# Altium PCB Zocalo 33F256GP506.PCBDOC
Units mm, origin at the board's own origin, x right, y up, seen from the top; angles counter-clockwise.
Board outline 80.87 x 74.55 mm, 2 copper layers (Top Layer, Bottom Layer); 8 components, 108 nets, 330 pads, 93 vias.
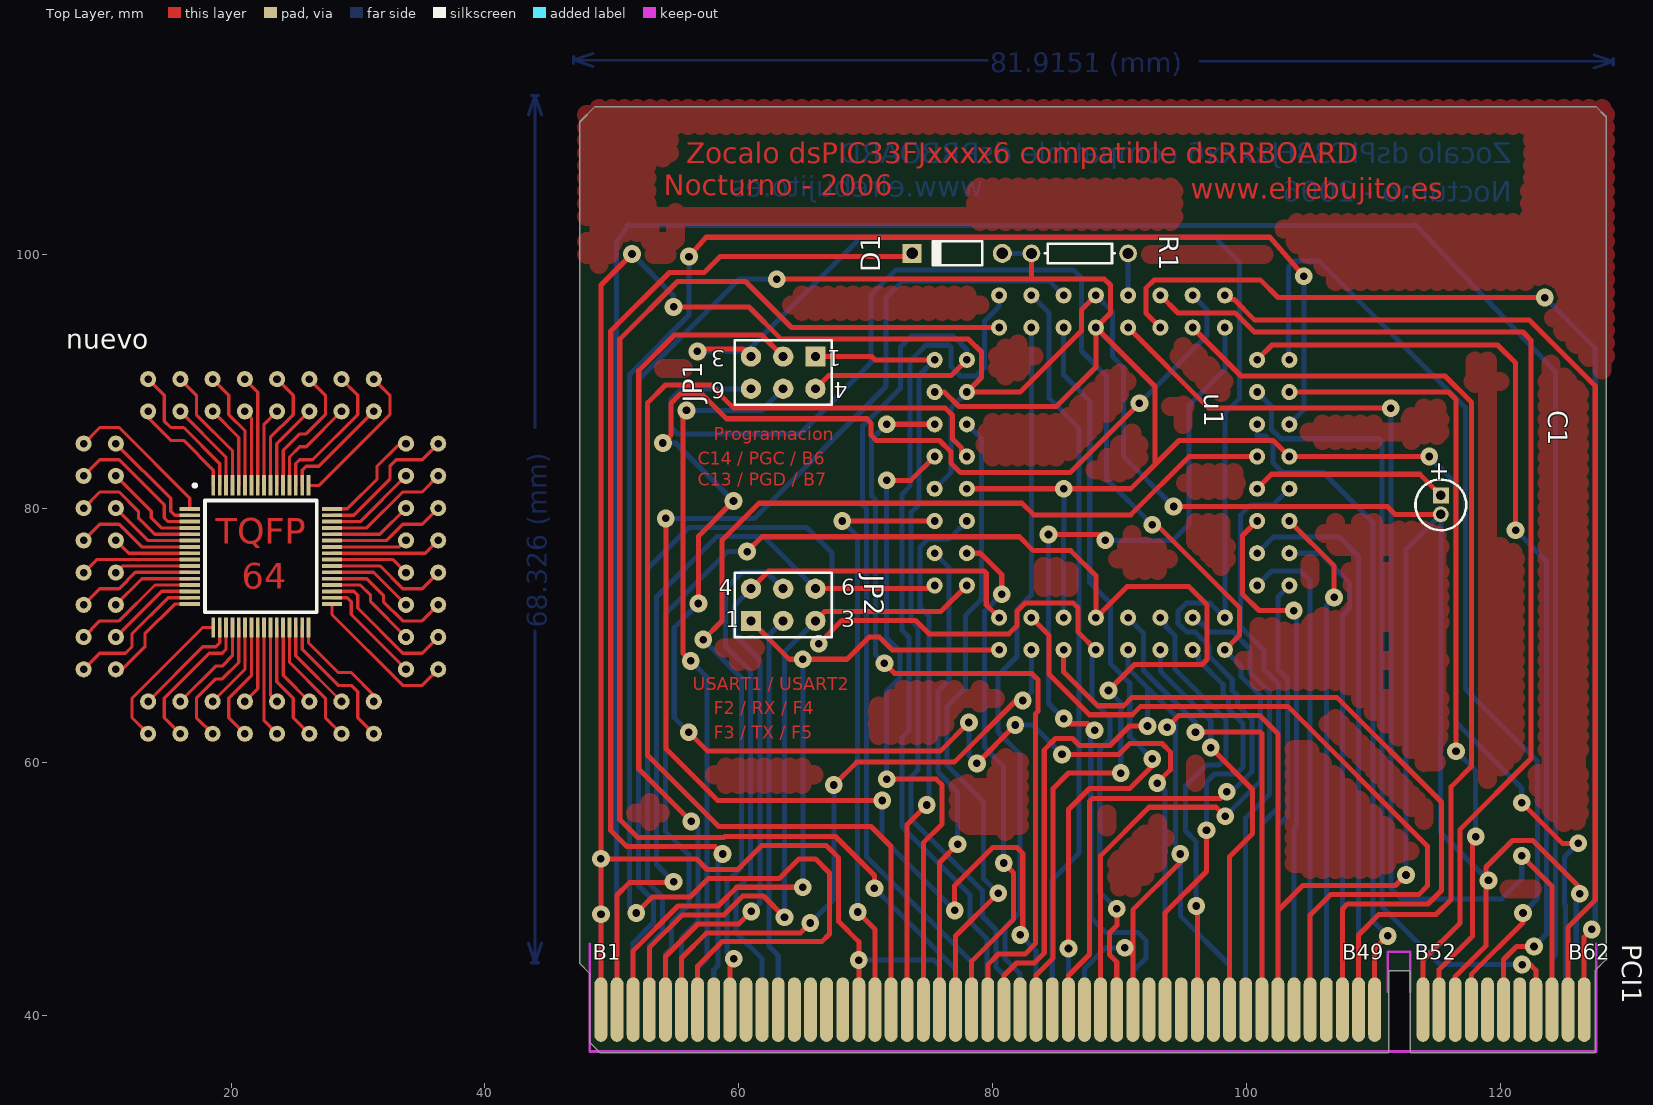
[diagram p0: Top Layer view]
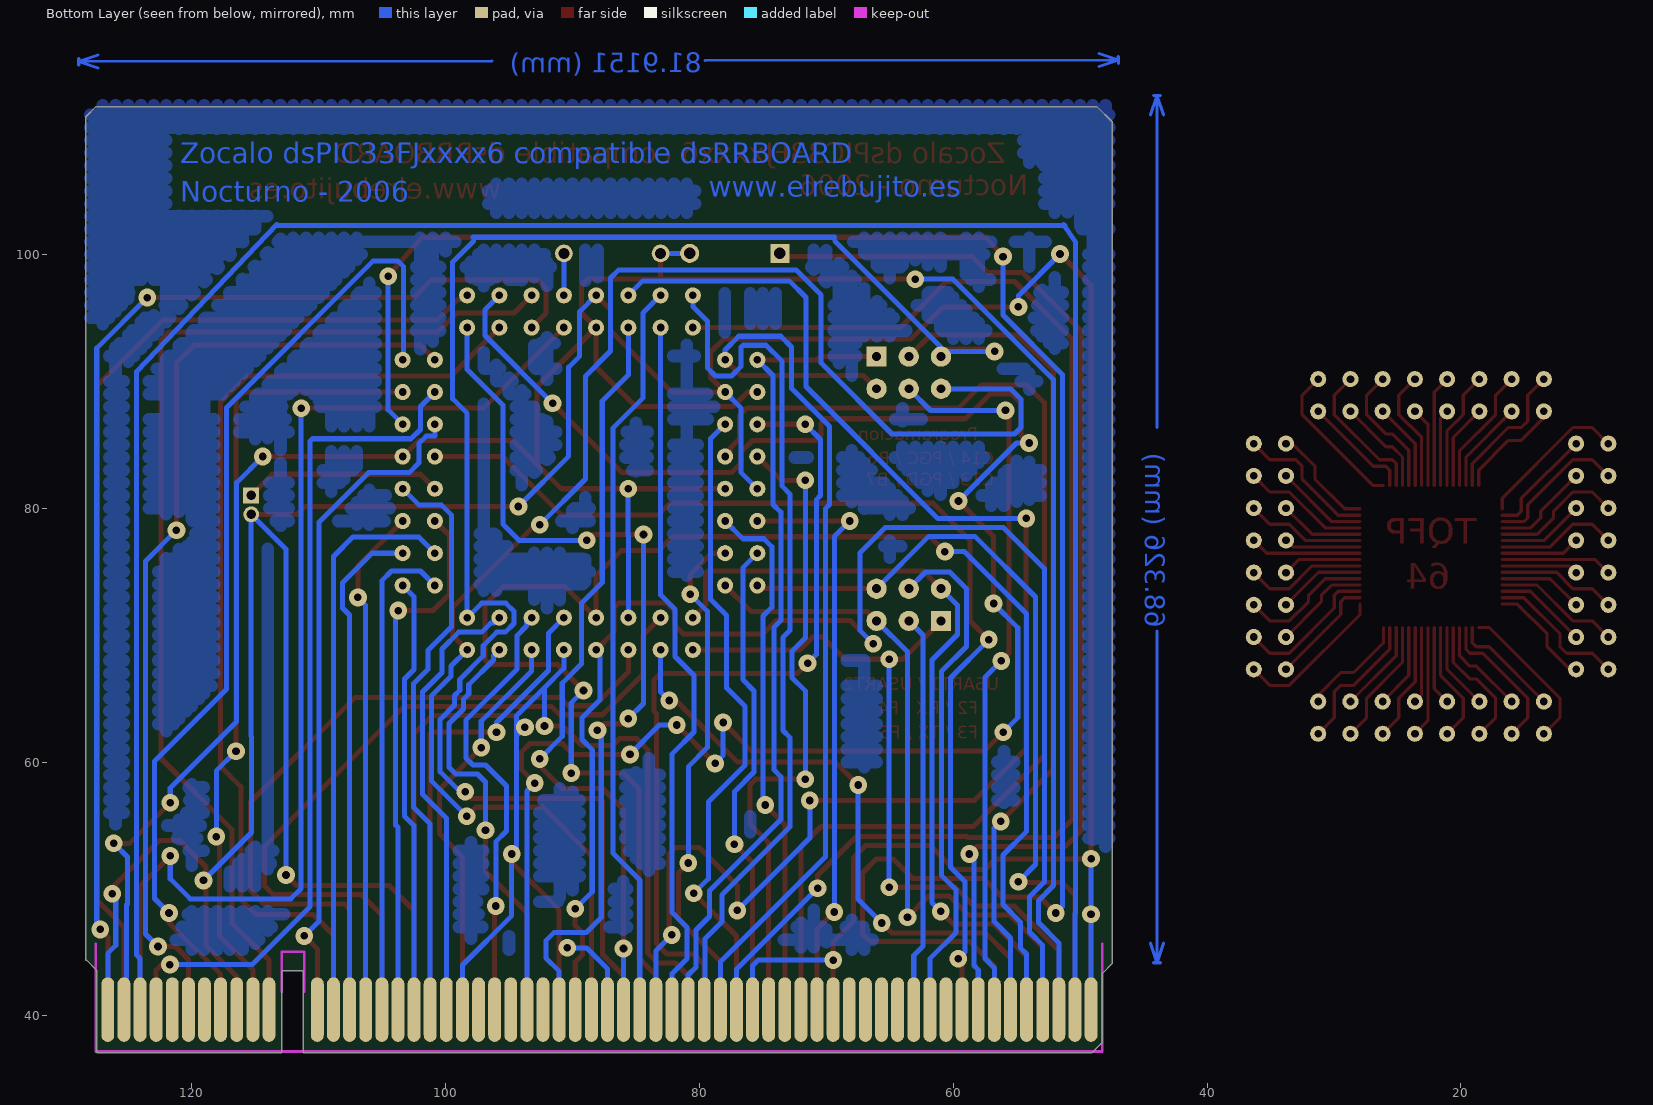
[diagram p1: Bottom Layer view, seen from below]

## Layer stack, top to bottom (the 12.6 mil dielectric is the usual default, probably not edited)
Top Layer: signal copper 0.0356
Dielectric: core 0.32, FR-4, Dk 4.8
Bottom Layer: signal copper 0.0356

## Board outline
128.35,44.4 128.35,110.85 127.55,111.65 48.675,111.65 47.475,110.45 47.475,44.125 48.25,43.35 48.25,37.925 49.075,37.1 111.2,37.1 111.2,43.575 112.9,43.575 112.9,37.1 127.475,37.1 127.475,43.575 128.3,44.4

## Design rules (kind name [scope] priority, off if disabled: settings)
Clearance [All] p1: gap=0.3
ComponentClearance [All] p1: gap=0.254 collisioncheckmode=0
HoleSize [All] p1: absolutevalues=TRUE maxlimit=2.54 minlimit=0.6 maxpercent=80.000 minpercent=20.000
PlaneConnect [All] p1: planeconnectstyle=Relief reliefexpansion=0.5 reliefentries=4 reliefconductorwidth=0.4 reliefairgap=0.3
PolygonConnect [All] p1: connectstyle=Relief reliefconductorwidth=0.4 reliefentries=4 polygonreliefangle="90 Angle"
RoutingLayers [All] p1: top layer=Horizontal bottom layer=Vertical
RoutingVias [All] p1: holewidth=0.6 width=1.4 viastyle="Through Hole" minholewidth=0.6 minwidth=1.4 maxholewidth=0.6 maxwidth=1.4
SolderMaskExpansion [All] p1: expansion=1
TestPointUsage [All] p1: valid=0 allowmultiple=FALSE
Testpoint [All] p1: side=15 testpointundercomponent=TRUE minsize=1.016 maxsize=2.54 preferedsize=1.524 minholesize=0 maxholesize=1.016 preferedholesize=0.813 testpointgrid=0.025 style=1023 order=1234567890
Width [All] p1: maxlimit=0.4 minlimit=0.254 preferedwidth=0.254 toplayer_minwidth=0.4 toplayer_prefwidth=0.4 bottomlayer_minwidth=0.4 bottomlayer_prefwidth=0.4 minimp=50.000000 maximp=50.000000 favimp=50.000000
14 further rules are at their usual default settings.

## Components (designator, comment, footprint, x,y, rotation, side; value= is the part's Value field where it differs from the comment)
C1 "Cap Pol1" CAPPR1.5-4X5 115.316,80.264 r270 top
D1 "BAT85" DIO7.1-3.9x1.9 77.216,100.076 r180 top
JP1 "Header 3X2A" HDR2X3_CEN 66.04,91.948 r180 top
JP2 "Header 3X2A" HDR2X3_CEN 60.96,71.12 r0 top
nuevo "Comment" "TQFP-64 con DIP" 22.352,76.2 r0 top
PCI1 "Conector PCI Macho" PCI_Macho 76.708,45.72 r0 top
R1 "Res1" AXIAL-0.3 86.868,100.076 r0 top
u1 "o33FJ256GP506" "TQFP-64 SOLO DIP" 89.408,82.804 r270 top

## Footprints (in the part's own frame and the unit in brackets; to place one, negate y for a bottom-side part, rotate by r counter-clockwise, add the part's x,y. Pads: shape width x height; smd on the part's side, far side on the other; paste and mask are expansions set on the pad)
AXIAL-0.3 [mm]
  round 1.4 hole 0.85: 1(-3.81,0) 2(3.81,0)
  silkscreen extent -2.77,-0.76 2.77,0.76
CAPPR1.5-4X5 [mm]
  rect 1.25x1.25 hole 0.75: 1(-0.75,0)
  round 1.25 hole 0.75: 2(0.75,0)
  silkscreen extent -2,-2 2,2
DIO7.1-3.9x1.9 [mm]
  round 1.5 hole 0.9: 1(-3.55,0)
  rect 1.5x1.5 hole 0.9: 2(3.55,0)
  silkscreen extent -1.95,-0.95 2.05,0.95
HDR2X3_CEN [mm] "Connector; Header; 3x2 Position"
  rect 1.6x1.6 hole 0.7: 1(0,0)
  round 1.6 hole 0.7: 2(2.54,0) 3(5.08,0) 4(0,2.54) 5(2.54,2.54) 6(5.08,2.54)
  silkscreen extent -1.27,-1.27 6.35,3.81
PCI_Macho [mil] "Conector PCI Macho"
  oval 40x200 smd far side: A1(-1085.31,-205.75) A2(-1035.31,-205.75) A3(-985.31,-205.75) A4(-935.31,-205.75) A5(-885.31,-205.75) A6(-835.31,-205.75) A7(-785.31,-205.75) A8(-735.31,-205.75) A9(-685.31,-205.75) A10(-635.31,-205.75) A11(-585.31,-205.75) A12(-535.31,-205.75) A13(-485.31,-205.75) A14(-435.31,-205.75) A15(-385.31,-205.75) A16(-335.31,-205.75) A17(-285.31,-205.75) A18(-235.31,-205.75) A19(-185.31,-205.75) A20(-135.31,-205.75) A21(-85.31,-205.75) A22(-35.31,-205.75) A23(14.69,-205.75) A24(64.69,-205.75) A25(114.69,-205.75) A26(164.69,-205.75) A27(214.69,-205.75) A28(264.69,-205.75) A29(314.69,-205.75) A30(364.69,-205.75) A31(414.69,-205.75) A32(464.69,-205.75) A33(514.69,-205.75) A34(564.69,-205.75) A35(614.69,-205.75) A36(664.69,-205.75) A37(714.69,-205.75) A38(764.69,-205.75) A39(814.69,-205.75) A40(864.69,-205.75) A41(914.69,-205.75) A42(964.69,-205.75) A43(1014.69,-205.75) A44(1064.69,-205.75) A45(1114.69,-205.75) A46(1164.69,-205.75) A47(1214.69,-205.75) A48(1264.69,-205.75) A49(1314.69,-205.75) A50(1464.69,-205.75) A51(1514.69,-205.75) A52(1564.69,-205.75) A53(1614.69,-205.75) A54(1664.69,-205.75) A55(1714.69,-205.75) A56(1764.69,-205.75) A57(1814.69,-205.75) A58(1864.69,-205.75) A59(1914.69,-205.75) A60(1964.69,-205.75)
  oval 40x200 smd: B1(-1085.31,-205.75) B2(-1035.31,-205.75) B3(-985.31,-205.75) B4(-935.31,-205.75) B5(-885.31,-205.75) B6(-835.31,-205.75) B7(-785.31,-205.75) B8(-735.31,-205.75) B9(-685.31,-205.75) B10(-635.31,-205.75) B11(-585.31,-205.75) B12(-535.31,-205.75) B13(-485.31,-205.75) B14(-435.31,-205.75) B15(-385.31,-205.75) B16(-335.31,-205.75) B17(-285.31,-205.75) B18(-235.31,-205.75) B19(-185.31,-205.75) B20(-135.31,-205.75) B21(-85.31,-205.75) B22(-35.31,-205.75) B23(14.69,-205.75) B24(64.69,-205.75) B25(114.69,-205.75) B26(164.69,-205.75) B27(214.69,-205.75) B28(264.69,-205.75) B29(314.69,-205.75) B30(364.69,-205.75) B31(414.69,-205.75) B32(464.69,-205.75) B33(514.69,-205.75) B34(564.69,-205.75) B35(614.69,-205.75) B36(664.69,-205.75) B37(714.69,-205.75) B38(764.69,-205.75) B39(814.69,-205.75) B40(864.69,-205.75) B41(914.69,-205.75) B42(964.69,-205.75) B43(1014.69,-205.75) B44(1064.69,-205.75) B45(1114.69,-205.75) B46(1164.69,-205.75) B47(1214.69,-205.75) B48(1264.69,-205.75) B49(1314.69,-205.75) B50(1464.69,-205.75) B51(1514.69,-205.75) B52(1564.69,-205.75) B53(1614.69,-205.75) B54(1664.69,-205.75) B55(1714.69,-205.75) B56(1764.69,-205.75) B57(1814.69,-205.75) B58(1864.69,-205.75) B59(1914.69,-205.75) B60(1964.69,-205.75)
  Keep-Out Layer lines w8: -1120.31,-0.75 -1120.31,-335.75 1998.63,-335.75 ; 1354.69,-150.75 1354.69,-25.75 1424.69,-25.75 1424.69,-150.75 ; 2002.57,-335.75 2002.57,-0.75
"TQFP-64 con DIP" [mm]
  round 1.27 hole 0.6: 1(-13.97,8.89) 2(-11.43,8.89) 3(-13.97,6.35) 4(-11.43,6.35) 5(-13.97,3.81) 6(-11.43,3.81) 7(-13.97,1.27) 8(-11.43,1.27) 9(-13.97,-1.27) 10(-11.43,-1.27) 11(-13.97,-3.81) 12(-11.43,-3.81) 13(-13.97,-6.35) 14(-11.43,-6.35) 15(-13.97,-8.89) 16(-11.43,-8.89) 17(-8.89,-13.97) 18(-8.89,-11.43) 19(-6.35,-13.97) 20(-6.35,-11.43) 21(-3.81,-13.97) 22(-3.81,-11.43) 23(-1.27,-13.97) 24(-1.27,-11.43) 25(1.27,-13.97) 26(1.27,-11.43) 27(3.81,-13.97) 28(3.81,-11.43) 29(6.35,-13.97) 30(6.35,-11.43) 31(8.89,-13.97) 32(8.89,-11.43) 33(13.97,-8.89) 34(11.43,-8.89) 35(13.97,-6.35) 36(11.43,-6.35) 37(13.97,-3.81) 38(11.43,-3.81) 39(13.97,-1.27) 40(11.43,-1.27) 41(13.97,1.27) 42(11.43,1.27) 43(13.97,3.81) 44(11.43,3.81) 45(13.97,6.35) 46(11.43,6.35) 47(13.97,8.89) 48(11.43,8.89) 49(8.89,13.97) 50(8.89,11.43) 51(6.35,13.97) 52(6.35,11.43) 53(3.81,13.97) 54(3.81,11.43) 55(1.27,13.97) 56(1.27,11.43) 57(-1.27,13.97) 58(-1.27,11.43) 59(-3.81,13.97) 60(-3.81,11.43) 61(-6.35,13.97) 62(-6.35,11.43) 63(-8.89,13.97) 64(-8.89,11.43)
  rect 1.6x0.3 smd: 1(-5.6,3.75) 2(-5.6,3.25) 3(-5.6,2.75) 4(-5.6,2.25) 5(-5.6,1.75) 6(-5.6,1.25) 7(-5.6,0.75) 8(-5.6,0.25) 9(-5.6,-0.25) 10(-5.6,-0.75) 11(-5.6,-1.25) 12(-5.6,-1.75) 13(-5.6,-2.25) 14(-5.6,-2.75) 15(-5.6,-3.25) 16(-5.6,-3.75) 33(5.6,-3.75) 34(5.6,-3.25) 35(5.6,-2.75) 36(5.6,-2.25) 37(5.6,-1.75) 38(5.6,-1.25) 39(5.6,-0.75) 40(5.6,-0.25) 41(5.6,0.25) 42(5.6,0.75) 43(5.6,1.25) 44(5.6,1.75) 45(5.6,2.25) 46(5.6,2.75) 47(5.6,3.25) 48(5.6,3.75)
  rect 0.3x1.6 smd: 17(-3.75,-5.6) 18(-3.25,-5.6) 19(-2.75,-5.6) 20(-2.25,-5.6) 21(-1.75,-5.6) 22(-1.25,-5.6) 23(-0.75,-5.6) 24(-0.25,-5.6) 25(0.25,-5.6) 26(0.75,-5.6) 27(1.25,-5.6) 28(1.75,-5.6) 29(2.25,-5.6) 30(2.75,-5.6) 31(3.25,-5.6) 32(3.75,-5.6) 49(3.75,5.6) 50(3.25,5.6) 51(2.75,5.6) 52(2.25,5.6) 53(1.75,5.6) 54(1.25,5.6) 55(0.75,5.6) 56(0.25,5.6) 57(-0.25,5.6) 58(-0.75,5.6) 59(-1.25,5.6) 60(-1.75,5.6) 61(-2.25,5.6) 62(-2.75,5.6) 63(-3.25,5.6) 64(-3.75,5.6)
  Top Layer lines w0.254: -13.97,-8.89 -12.7,-7.62 -10.668,-7.62 -10.16,-7.112 -10.16,-6.096 -7.314,-3.25 -6.298,-3.25 -5.6,-3.25 ; -13.97,-6.35 -12.7,-5.08 -11.176,-5.08 -8.346,-2.25 -5.6,-2.25 ; -13.97,-3.81 -12.7,-2.54 -11.176,-2.54 -9.886,-1.25 -5.6,-1.25 ; -13.97,-1.27 -12.95,-0.25 -5.6,-0.25 ; -13.97,1.27 -12.7,2.54 -11.176,2.54 -9.386,0.75 -5.6,0.75 ; -13.97,3.81 -12.7,5.08 -11.176,5.08 -9.652,3.556 -9.652,3.048 -8.354,1.75 -5.6,1.75 ; -13.97,6.35 -12.7,7.62 -11.176,7.62 -7.62,4.064 -7.62,3.048 -7.322,2.75 -5.6,2.75 ; -13.97,8.89 -12.7,10.16 -11.176,10.16 -5.6,4.584 -5.6,3.75 ; -11.43,-8.89 -10.922,-8.89 -9.144,-7.112 -9.144,-6.096 -6.798,-3.75 -5.6,-3.75 ; -11.43,-6.35 -7.83,-2.75 -5.6,-2.75 ; -11.43,-3.81 -9.37,-1.75 -5.6,-1.75 ; -11.43,-1.27 -10.91,-0.75 -5.6,-0.75 ; -11.43,1.27 -10.41,0.25 -5.6,0.25 ; -11.43,3.81 -8.87,1.25 -5.6,1.25 ; -11.43,6.35 -8.636,3.556 -8.636,3.048 -7.838,2.25 -5.6,2.25 ; -11.43,8.89 -7.112,4.572 -7.112,3.556 -6.806,3.25 -5.6,3.25 ; -8.89,-13.97 -10.16,-12.7 -10.16,-11.176 -4.584,-5.6 -3.75,-5.6 ; -8.89,-11.43 -4.572,-7.112 -3.556,-7.112 -3.25,-6.806 -3.25,-5.6 ; -8.89,11.43 -8.89,10.922 -7.112,9.144 -6.096,9.144 -3.75,6.798 -3.75,5.6 ; -8.89,13.97 -7.62,12.7 -7.62,10.668 -7.112,10.16 -6.096,10.16 -3.25,7.314 -3.25,6.298 -3.25,5.6 ; -6.35,-13.97 -7.62,-12.7 -7.62,-11.176 -4.064,-7.62 -3.048,-7.62 -2.75,-7.322 -2.75,-5.6 ; -6.35,-11.43 -3.556,-8.636 -3.048,-8.636 -2.25,-7.838 -2.25,-5.6 ; -6.35,11.43 -2.75,7.83 -2.75,5.6 ; -6.35,13.97 -5.08,12.7 -5.08,11.176 -2.25,8.346 -2.25,5.6 ; -3.81,-13.97 -5.08,-12.7 -5.08,-11.176 -3.556,-9.652 -3.048,-9.652 -1.75,-8.354 -1.75,-5.6 ; -3.81,-11.43 -1.25,-8.87 -1.25,-5.6 ; -3.81,11.43 -1.75,9.37 -1.75,5.6 ; -3.81,13.97 -2.54,12.7 -2.54,11.176 -1.25,9.886 -1.25,5.6 ; -1.27,-13.97 -2.54,-12.7 -2.54,-11.176 -0.75,-9.386 -0.75,-5.6 ; -1.27,-11.43 -0.25,-10.41 -0.25,-5.6 ; -1.27,11.43 -0.75,10.91 -0.75,5.6 ; -1.27,13.97 -0.25,12.95 -0.25,5.6 ; 0.25,-5.6 0.25,-12.95 1.27,-13.97 ; 0.25,5.6 0.25,10.41 1.27,11.43 ; 0.75,-5.6 0.75,-10.91 1.27,-11.43 ; 0.75,5.6 0.75,9.386 2.54,11.176 2.54,12.7 1.27,13.97 ; 1.25,-5.6 1.25,-9.886 2.54,-11.176 2.54,-12.7 3.81,-13.97 ; 1.25,5.6 1.25,8.87 3.81,11.43 ; 1.75,-5.6 1.75,-9.37 3.81,-11.43 ; 1.75,5.6 1.75,8.354 3.048,9.652 3.556,9.652 5.08,11.176 5.08,12.7 3.81,13.97 ; 2.25,-5.6 2.25,-8.346 5.08,-11.176 5.08,-12.7 6.35,-13.97 ; 2.25,5.6 2.25,7.838 3.048,8.636 3.556,8.636 6.35,11.43 ; 2.75,-5.6 2.75,-7.83 6.35,-11.43 ; 2.75,5.6 2.75,7.322 3.048,7.62 4.064,7.62 7.62,11.176 7.62,12.7 6.35,13.97 ; 3.25,-5.6 3.25,-6.298 3.25,-7.314 6.096,-10.16 7.112,-10.16 7.62,-10.668 7.62,-12.7 8.89,-13.97 ; 3.25,5.6 3.25,6.806 3.556,7.112 4.572,7.112 8.89,11.43 ; 3.75,-5.6 3.75,-6.798 6.096,-9.144 7.112,-9.144 8.89,-10.922 8.89,-11.43 ; 3.75,5.6 4.584,5.6 10.16,11.176 10.16,12.7 8.89,13.97 ; 5.6,-3.75 5.6,-4.584 11.176,-10.16 12.7,-10.16 13.97,-8.89 ; 5.6,-3.25 6.806,-3.25 7.112,-3.556 7.112,-4.572 11.43,-8.89 ; 5.6,-2.75 7.322,-2.75 7.62,-3.048 7.62,-4.064 11.176,-7.62 12.7,-7.62 13.97,-6.35 ; 5.6,-2.25 7.838,-2.25 8.636,-3.048 8.636,-3.556 11.43,-6.35 ; 5.6,-1.75 8.354,-1.75 9.652,-3.048 9.652,-3.556 11.176,-5.08 12.7,-5.08 13.97,-3.81 ; 5.6,-1.25 8.87,-1.25 11.43,-3.81 ; 5.6,-0.75 9.386,-0.75 11.176,-2.54 12.7,-2.54 13.97,-1.27 ; 5.6,-0.25 10.41,-0.25 11.43,-1.27 ; 5.6,0.25 12.95,0.25 13.97,1.27 ; 5.6,0.75 10.91,0.75 11.43,1.27 ; 5.6,1.25 9.886,1.25 11.176,2.54 12.7,2.54 13.97,3.81 ; 5.6,1.75 9.37,1.75 11.43,3.81 ; 5.6,2.25 8.346,2.25 11.176,5.08 12.7,5.08 13.97,6.35 ; 5.6,2.75 7.83,2.75 11.43,6.35 ; 5.6,3.25 6.298,3.25 7.314,3.25 10.16,6.096 10.16,7.112 10.668,7.62 12.7,7.62 13.97,8.89 ; 5.6,3.75 6.798,3.75 9.144,6.096 9.144,7.112 10.922,8.89 11.43,8.89
  silkscreen extent -5.33,-4.4 4.4,5.71
"TQFP-64 SOLO DIP" [mm]
  round 1.27 hole 0.6: 1(-13.97,8.89) 2(-11.43,8.89) 3(-13.97,6.35) 4(-11.43,6.35) 5(-13.97,3.81) 6(-11.43,3.81) 7(-13.97,1.27) 8(-11.43,1.27) 9(-13.97,-1.27) 10(-11.43,-1.27) 11(-13.97,-3.81) 12(-11.43,-3.81) 13(-13.97,-6.35) 14(-11.43,-6.35) 15(-13.97,-8.89) 16(-11.43,-8.89) 17(-8.89,-13.97) 18(-8.89,-11.43) 19(-6.35,-13.97) 20(-6.35,-11.43) 21(-3.81,-13.97) 22(-3.81,-11.43) 23(-1.27,-13.97) 24(-1.27,-11.43) 25(1.27,-13.97) 26(1.27,-11.43) 27(3.81,-13.97) 28(3.81,-11.43) 29(6.35,-13.97) 30(6.35,-11.43) 31(8.89,-13.97) 32(8.89,-11.43) 33(13.97,-8.89) 34(11.43,-8.89) 35(13.97,-6.35) 36(11.43,-6.35) 37(13.97,-3.81) 38(11.43,-3.81) 39(13.97,-1.27) 40(11.43,-1.27) 41(13.97,1.27) 42(11.43,1.27) 43(13.97,3.81) 44(11.43,3.81) 45(13.97,6.35) 46(11.43,6.35) 47(13.97,8.89) 48(11.43,8.89) 49(8.89,13.97) 50(8.89,11.43) 51(6.35,13.97) 52(6.35,11.43) 53(3.81,13.97) 54(3.81,11.43) 55(1.27,13.97) 56(1.27,11.43) 57(-1.27,13.97) 58(-1.27,11.43) 59(-3.81,13.97) 60(-3.81,11.43) 61(-6.35,13.97) 62(-6.35,11.43) 63(-8.89,13.97) 64(-8.89,11.43)

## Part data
C1: "Polarized Capacitor (Radial)"
D1: library part "Diode 1N4148", "High Conductance Fast Diode"
JP1 JP2: "Header, 3-Pin, Dual row"
R1: "Resistor"

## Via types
v1: diameter 1.4, hole 0.6, Top Layer to Bottom Layer, 93 vias

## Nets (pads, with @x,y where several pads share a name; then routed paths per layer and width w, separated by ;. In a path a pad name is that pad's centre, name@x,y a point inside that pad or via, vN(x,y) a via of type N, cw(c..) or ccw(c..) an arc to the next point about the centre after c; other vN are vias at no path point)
A0: PCI1.A14
A1: PCI1.A16
A2: PCI1.A18
A3: PCI1.A20
A4: PCI1.A21
A5: PCI1.A19
A6: PCI1.A17
A7: PCI1.A15
A9: PCI1.B15
A10: PCI1.B13
A12: PCI1.B11
A13: PCI1.B12
A14: PCI1.B14
A15: PCI1.B16
B0: PCI1.A23 u1.16 | length 106.3
  Top Layer w0.4: v1(70.688,50.063) 70.688,51.054 67.615,54.127 58.903,54.127 58.826,54.051 52.045,54.051 50.622,55.474 50.622,93.32 55.169,97.866 60.528,97.866 64.16,94.234 u1.16
  Bottom Layer w0.4: v1(70.688,50.063) 77.081,43.67 PCI1.A23
B1: PCI1.A25 u1.15 | length 69.3
  Bottom Layer w0.4: PCI1.A25 79.621,42.85 79.553,42.918 79.553,46.076 78.232,47.396 78.232,49.53 72.873,54.889 72.873,61.951 73.406,62.484 73.406,69.825 72.873,70.358 72.873,81.128 73.482,81.737 73.482,91.572 74.747,92.837 76.573,92.837 76.708,92.702 76.708,91.186 77.47,90.424 78.74,90.424 79.375,91.059 79.375,94.742 80.518,95.885 u1.15
B2: PCI1.A27 u1.14 | length 56.5
  Bottom Layer w0.4: PCI1.A27 82.161,43.331 80.966,44.526 80.966,46.965 82.144,48.142 82.144,60.647 80.416,62.375 80.416,66.827 81.915,68.326 81.915,72.034 83.058,73.177 u1.14
B3: PCI1.A29 u1.13 | length 58.7
  Bottom Layer w0.4: u1.13 84.455,95.377 84.455,88.671 86.817,86.309 86.817,52.832 84.701,50.716 PCI1.A29
B4: PCI1.A30 u1.12 | length 61.2
  Top Layer w0.4: v1(85.979,45.314) 85.979,56.261 87.63,57.912 90.805,57.912 92.583,59.69 v1(92.583,60.249)
  Bottom Layer w0.4: u1.12 85.598,90.5 87.655,88.443 87.655,74.143 89.281,72.517 89.281,67.742 90.805,66.218 90.805,62.027 v1(92.583,60.249) ; PCI1.A30 85.971,45.306 v1(85.979,45.314)
B5: PCI1.A28 u1.11 | length 113.2
  Top Layer w0.4: v1(54.254,79.197) 54.254,61.062 58.344,56.972 v1(71.298,56.972) ; v1(77.013,48.311) 77.013,50.267 80.01,53.264 81.915,53.264 82.372,52.807 82.372,46.584 v1(82.169,46.38)
  Bottom Layer w0.4: v1(54.254,79.197) 61.214,79.197 71.603,89.586 71.603,96.596 72.923,97.917 84.455,97.917 u1.11 ; v1(71.298,56.972) 71.298,54.026 v1(77.013,48.311) ; v1(82.169,46.38) 83.431,45.118 PCI1.A28
B6: JP1.1 PCI1.A26 u1.17 | length 64.9
  Top Layer w0.4: JP1.1 70.485,91.948 70.739,91.694 u1.17
  Bottom Layer w0.4: u1.17 74.193,90.449 74.193,80.289 73.584,79.68 73.584,71.145 74.117,70.612 74.117,59.385 73.584,58.852 73.584,55.474 79.197,49.86 79.197,47.828 80.264,46.761 80.264,43.84 80.891,43.213 PCI1.A26
B7: JP1.4 PCI1.A24 u1.18 | length 76.7
  Top Layer w0.4: JP1.4 67.081,90.449 76.733,90.449 u1.18
  Bottom Layer w0.4: u1.18 77.978,92.469 76.898,93.548 73.584,93.548 72.746,92.71 72.746,89.446 69.748,86.449 69.748,80.289 70.079,79.959 70.079,52.519 78.351,44.247 PCI1.A24
B8/H0: PCI1.B25 u1.21 | length 65
  Top Layer w0.4: v1(71.476,67.793) 72.288,66.98 83.083,66.98 83.591,66.472 83.591,64.008 83.369,63.786 83.369,45.688 82.563,44.882 80.467,44.882 79.621,44.036 PCI1.B25 ; v1(71.653,86.614) u1.21
  Bottom Layer w0.4: v1(71.476,67.793) 70.79,68.478 70.79,80.664 70.453,81.001 70.453,85.414 v1(71.653,86.614)
B9/H1: PCI1.B23 u1.22 | length 50.8
  Top Layer w0.4: PCI1.B23 77.081,46.296 v1(80.442,49.657)
  Bottom Layer w0.4: u1.22 79.121,85.471 79.121,72.822 77.851,71.552 77.851,65.837 76.403,64.389 76.403,59.741 79.299,56.845 79.299,50.8 v1(80.442,49.657)
B10/H2: PCI1.B21 u1.23 | length 51.8
  Top Layer w0.4: v1(71.653,58.649) 75.565,58.649 76.022,58.191 76.022,55.126 74.541,53.645 PCI1.B21 ; v1(71.653,82.194) 73.558,82.194 u1.23
  Bottom Layer w0.4: v1(71.653,58.649) 71.653,65.608 72.695,66.65 72.695,68.732 71.653,69.774 v1(71.653,82.194)
B11/H3: PCI1.B19 u1.24 | length 92.3
  Top Layer w0.4: PCI1.B19 72.001,53.34 70.426,54.915 58.42,54.915 52.826,60.509 52.826,88.31 54.229,89.713 57.785,89.713 59.614,87.884 76.276,87.884 76.835,87.325 76.835,85.471 77.546,84.76 77.546,84.074 u1.24
B12/H4: PCI1.B18 u1.27 | length 46.9
  Top Layer w0.4: v1(68.148,78.994) u1.27 ; v1(69.367,48.184) 70.731,46.82 PCI1.B18
  Bottom Layer w0.4: v1(68.148,78.994) 69.367,77.775 v1(69.367,48.184)
B13/H5: PCI1.B20 u1.28 | length 42
  Top Layer w0.4: PCI1.B20 73.271,55.085 v1(74.803,56.617)
  Bottom Layer w0.4: v1(74.803,56.617) 74.981,56.794 74.981,71.501 74.295,72.187 74.295,76.962 74.93,77.597 76.581,77.597 u1.28
B14/H6: PCI1.B22 u1.29 | length 38
  Top Layer w0.4: PCI1.B22 75.811,52.095 v1(77.241,53.526)
  Bottom Layer w0.4: u1.29 76.581,75.311 76.581,66.495 75.692,65.606 75.692,59.207 77.241,57.658 v1(77.241,53.526)
B15/H7: PCI1.B24 u1.30 | length 40.6
  Top Layer w0.4: u1.30 79.045,76.454 80.721,74.778 v1(80.721,73.228) ; PCI1.B24 78.351,44.315 81.661,47.625 81.661,51.257 v1(80.874,52.045)
  Bottom Layer w0.4: v1(80.721,73.228) 79.375,71.882 79.375,61.138 80.874,59.639 v1(80.874,52.045)
C0: PCI1.A32
C1: PCI1.A34 u1.2 | length 72.1
  Top Layer w0.4: v1(84.404,77.927) 88.417,77.927 v1(88.875,77.47) ; v1(85.598,63.424) 86.004,63.017 87.528,63.017 v1(88.036,62.509)
  Bottom Layer w0.4: v1(84.404,77.927) 84.404,64.618 v1(85.598,63.424) ; v1(88.036,62.509) 87.732,62.205 87.732,47.752 88.9,46.584 91.44,46.584 92.1,45.923 92.1,44.559 91.051,43.51 PCI1.A34 ; v1(88.875,77.47) 94.209,77.47 95.479,78.74 95.479,88.113 98.298,90.932 u1.2
C2: PCI1.A36 u1.3 | length 152
  Top Layer w0.4: v1(54.026,85.141) 54.661,85.776 54.661,88.265 55.397,89.002 57.074,89.002 59.03,87.046 70.085,87.046 70.434,86.697 70.434,85.744 70.834,85.344 75.819,85.344 76.708,84.455 76.708,83.566 77.47,82.804 86.106,82.804 v1(91.567,88.265) ; v1(56.058,62.357) 57.556,60.858 75.87,60.858 v1(78.13,63.119) ; v1(56.82,72.492) 56.82,77.8 v1(59.588,80.569) ; v1(78.765,59.893) v1(81.788,62.916) ; v1(85.471,60.604) 89.941,60.604 90.805,61.468 93.345,61.468 94.005,60.808 94.005,59.385 v1(92.964,58.344)
  Bottom Layer w0.4: v1(54.026,85.141) 55.016,85.141 v1(59.588,80.569) ; v1(56.058,62.357) 54.915,63.5 54.915,70.587 v1(56.82,72.492) ; v1(78.13,63.119) 78.13,60.528 v1(78.765,59.893) ; v1(81.788,62.916) 83.16,62.916 v1(85.471,60.604) ; v1(91.567,88.265) 96.901,93.599 96.901,95.631 u1.3 ; v1(92.964,58.344) 93.591,57.717 PCI1.A36
C3: PCI1.A38
C4: PCI1.A39
C5: PCI1.A37
C6: PCI1.A35
C7: PCI1.A33
C12: PCI1.A4 PCI1.B33 u1.39 | length 117.9
  Top Layer w0.4: v1(66.294,69.317) 68.123,71.145 73.939,71.145 74.981,70.104 81.28,70.104 81.915,70.739 81.915,71.882 82.55,72.517 86.36,72.517 86.741,72.136 86.741,70.231 u1.39 ; PCI1.B33 89.781,44.247 89.216,44.812 89.216,46.558 89.789,47.131 v1(89.789,48.438)
  Bottom Layer w0.4: PCI1.A4 52.951,45.568 54,46.617 54,49.378 52.807,50.571 52.807,75.235 56.058,78.486 65.354,78.486 67.361,76.479 67.361,70.383 v1(66.294,69.317) ; u1.39 88.138,68.682 87.833,68.682 87.833,64.909 89.256,63.486 89.256,61.773 88.443,60.96 88.443,49.784 v1(89.789,48.438)
C13: JP1.6 PCI1.B32 u1.47 | length 124.6
  Top Layer w0.4: PCI1.B32 88.511,52.621 92.329,56.439 97.612,56.439 v1(98.323,55.728) ; v1(92.583,78.689) 92.939,78.689 99.441,72.187 99.441,69.977 u1.47
  Bottom Layer w0.4: JP1.6 55.486,89.408 54.661,88.582 54.661,86.36 55.169,85.852 64.821,85.852 70.409,91.44 70.409,96.799 72.39,98.781 86.36,98.781 86.995,98.146 86.995,92.38 88.976,90.399 88.976,82.296 v1(92.583,78.689) ; u1.47 99.568,67.564 99.568,66.763 101.122,65.21 101.122,58.526 v1(98.323,55.728)
C14: JP1.3 PCI1.B30 u1.48 | length 130.7
  Top Layer w0.4: v1(56.744,92.354) 56.921,92.532 60.376,92.532 JP1.3 ; PCI1.B30 85.971,43.18 87.63,44.839 87.63,56.921 87.852,57.144 97.936,57.144 v1(98.45,57.658)
  Bottom Layer w0.4: v1(56.744,92.354) 60.63,92.354 69.317,101.041 ; 69.342,101.346 97.815,101.346 ; 97.79,101.041 99.441,99.39 99.441,88.621 98.298,87.478 u1.48 97.155,72.517 95.25,72.517 94.615,71.882 94.615,70.912 95.296,70.231 95.966,70.231 97.028,69.169 97.028,68.368 98.882,66.514 98.882,65.659 99.289,65.253 99.289,64.491 100.422,63.358 100.422,59.239 98.841,57.658 v1(98.45,57.658)
C15: PCI1.A5 PCI1.B28 u1.40 | length 127.9
  Top Layer w0.4: v1(60.655,76.581) 61.824,77.749 82.118,77.749 83.21,76.657 86.157,76.657 88.138,74.676 u1.40 90.602,73.838 95.453,73.838 96.901,72.39 96.901,68.072 96.52,67.691 91.186,67.691 v1(89.129,65.634) ; PCI1.B28 83.431,43.223 84.769,44.561 84.769,57.921 85.979,59.131 v1(90.094,59.131)
  Bottom Layer w0.4: PCI1.A5 54.221,44.882 54.712,45.372 54.712,47.396 56.083,48.768 56.083,52.68 54.215,54.548 54.215,71.665 59.131,76.581 v1(60.655,76.581) ; v1(89.129,65.634) 90.094,64.668 v1(90.094,59.131)
D0: PCI1.A41 u1.46 | length 35.4
  Bottom Layer w0.4: u1.46 96.19,70.942 96.444,70.942 97.155,70.231 98.958,70.231 100.279,68.91 100.279,67.056 101.822,65.514 101.822,57.468 99.941,55.587 PCI1.A41
D1: PCI1.A43 u1.49 | length 34.4
  Bottom Layer w0.4: PCI1.A43 102.481,54.983 103.226,55.728 103.226,66.548 102.489,67.285 102.489,73.025 u1.49
D2: PCI1.A45 u1.50 | length 38.8
  Bottom Layer w0.4: u1.50 101.981,75.057 104.259,75.057 105.021,74.295 PCI1.A45
D3: PCI1.A47 u1.51 | length 39.6
  Bottom Layer w0.4: u1.51 105.791,76.454 108.128,74.117 108.128,72.144 107.561,71.577 PCI1.A47
D4: PCI1.A48 u1.52 | length 44.9
  Bottom Layer w0.4: u1.52 102.108,77.724 107.307,77.724 108.831,76.2 PCI1.A48
D5: PCI1.A46 u1.53 | length 40.2
  Top Layer w0.4: u1.53 106.909,75.463 v1(106.909,72.974)
  Bottom Layer w0.4: PCI1.A46 106.291,72.357 v1(106.909,72.974)
D6: PCI1.A44 u1.54 | length 42.4
  Top Layer w0.4: u1.54 99.695,77.851 99.695,73.228 100.99,71.933 v1(103.734,71.933)
  Bottom Layer w0.4: v1(103.734,71.933) 103.937,71.73 103.937,55.042 103.751,54.856 PCI1.A44
D7: PCI1.A42 u1.55 | length 45.4
  Bottom Layer w0.4: PCI1.A42 101.211,55.128 102.522,56.439 102.522,66.167 101.397,67.292 101.397,68.783 99.543,70.637 99.543,79.477 100.33,80.264 102.108,80.264 u1.55
D8/J0: PCI1.B42 u1.42 | length 38.2
  Top Layer w0.4: v1(95.987,62.357) 101.084,62.357 101.211,62.23 PCI1.B42
  Bottom Layer w0.4: u1.42 91.897,70.155 91.897,67.208 95.987,63.119 v1(95.987,62.357)
D9/J1: PCI1.B40 u1.43 | length 32.1
  Top Layer w0.4: v1(97.187,61.138) 100.482,57.842 100.482,54.356 98.671,52.545 PCI1.B40
  Bottom Layer w0.4: u1.43 93.218,67.183 97.187,63.214 v1(97.187,61.138)
D10/J2: PCI1.B38 u1.44 | length 35.3
  Top Layer w0.4: v1(96.037,48.659) 96.131,48.565 PCI1.B38
  Bottom Layer w0.4: u1.44 93.624,70.968 93.624,70.714 94.361,69.977 94.361,67.335 98.4,63.297 98.4,60.325 97.841,59.766 96.85,59.766 95.199,58.115 95.199,54.559 96.037,53.721 v1(96.037,48.659)
D11/J3: PCI1.B36 u1.45 | length 33.5
  Top Layer w0.4: PCI1.B36 93.591,48.125 96.85,51.384 v1(96.85,54.635)
  Bottom Layer w0.4: u1.45 96.215,68.377 96.215,68.047 98.171,66.091 98.171,65.363 98.587,64.948 98.587,64.178 99.72,63.044 99.72,59.581 99.195,59.055 97.485,59.055 96.85,58.42 v1(96.85,54.635)
D12/J4: PCI1.B35
D13/J5: PCI1.B37
D14/J6: PCI1.B39
D15/J7: PCI1.B41
D+: PCI1.A9
D-: PCI1.A10
E0: PCI1.A50
E1: PCI1.A52
E2: PCI1.A54
E3: PCI1.A56
E4: PCI1.A57
E5: PCI1.A55
E6: PCI1.A53
E7: PCI1.A51
E8: PCI1.B27
E9: PCI1.B29
F0: PCI1.B9 u1.58 | length 85.3
  Top Layer w0.4: v1(57.201,69.647) 58.674,71.12 58.674,77.47 61.595,80.391 82.321,80.391 83.236,79.477 90.894,79.477 95.492,84.074 u1.58 ; PCI1.B9 59.301,44.188 v1(59.614,44.501)
  Bottom Layer w0.4: v1(57.201,69.647) 60.223,66.624 60.223,51.714 59.08,50.571 59.08,45.034 v1(59.614,44.501)
F1: PCI1.B7 u1.59 | length 153.7
  Top Layer w0.4: v1(51.918,48.108) 53.181,49.371 56.153,49.371 57.62,50.838 63.208,50.838 64.745,52.375 66.04,52.375 67.158,51.257 67.158,46.457 66.548,45.847 58.674,45.847 56.761,43.934 PCI1.B7 ; v1(56.083,99.822) 57.404,101.346 101.854,101.346 v1(104.521,98.273)
  Bottom Layer w0.4: v1(51.918,48.108) 51.384,48.641 51.384,90.526 56.083,95.225 v1(56.083,99.822) ; u1.59 104.521,87.757 v1(104.521,98.273)
F2: JP2.4 PCI1.B5 u1.34 | length 62.6
  Top Layer w0.4: PCI1.B5 54.221,44.674 56.794,47.247 59.998,47.247 v1(60.985,48.235) ; JP2.4 62.357,75.057 79.324,75.057 79.502,74.879 79.502,72.39 u1.34
  Bottom Layer w0.4: JP2.4 59.66,72.36 59.66,70.058 61.671,68.047 61.671,48.92 v1(60.985,48.235)
F3: JP2.1 PCI1.B3 u1.33 | length 60
  Top Layer w0.4: PCI1.B3 51.681,45.128 55.22,48.666 58.369,48.666 59.841,50.138 v1(65.049,50.138) ; JP2.1 63.983,68.097 v1(65.049,68.097) 68.529,68.097 70.282,69.85 71.069,69.85 72.085,68.834 u1.33
  Bottom Layer w0.4: v1(65.049,50.138) v1(65.049,68.097)
F4: JP2.6 PCI1.B2 u1.31 | length 62.6
  Top Layer w0.4: PCI1.B2 50.411,49.53 51.376,50.495 54.788,50.495 v1(54.864,50.571) ; JP2.6 75.184,73.66 u1.31
  Bottom Layer w0.4: v1(54.864,50.571) 53.515,51.921 53.515,73 58.296,77.781 61.919,77.781 JP2.6
F5: JP2.3 PCI1.B4 u1.32 | length 55.3
  Top Layer w0.4: PCI1.B4 52.951,45.364 55.542,47.955 58.826,47.955 60.31,49.438 61.941,49.438 v1(63.602,47.777) ; JP2.3 66.777,71.857 75.921,71.857 u1.32
  Bottom Layer w0.4: v1(63.602,47.777) 63.602,68.682 JP2.3
F6: PCI1.B6 u1.35 | length 48.9
  Top Layer w0.4: PCI1.B6 55.491,44.558 57.48,46.547 64.86,46.547 v1(65.634,47.32) ; v1(67.488,58.191) 69.291,59.995 76.987,59.995 81.839,64.846 v1(82.372,64.846)
  Bottom Layer w0.4: v1(65.634,47.32) 67.488,49.174 v1(67.488,58.191) ; v1(82.372,64.846) 83.058,65.532 u1.35
F7: PCI1.B8
F8: PCI1.B31
G0: PCI1.B51 u1.61 | length 63.3
  Top Layer w0.4: u1.61 115.926,89.154 116.51,88.57 v1(116.51,60.858) ; PCI1.B51 115.181,43.655 117.805,46.279 117.805,53.873 v1(118.059,54.127)
  Bottom Layer w0.4: v1(116.51,60.858) 118.059,59.309 v1(118.059,54.127)
G1: PCI1.B49 u1.60 | length 53.1
  Top Layer w0.4: PCI1.B49 110.101,45.28 v1(111.125,46.304)
  Bottom Layer w0.4: u1.60 100.838,85.674 101.524,85.674 102.108,85.09 102.108,83.566 102.87,82.804 106.07,82.804 109.957,78.918 109.957,47.473 v1(111.125,46.304)
G2: PCI1.B47 u1.37 | length 59.6
  Top Layer w0.4: u1.37 85.598,67.101 88.265,64.434 90.322,64.434 90.989,65.1 107.112,65.1 115.367,56.845 115.367,49.886 114.3,48.819 107.95,48.819 107.561,48.43 PCI1.B47
G3: PCI1.B45 u1.36 | length 61.8
  Top Layer w0.4: u1.36 84.455,69.977 84.455,66.904 87.63,63.729 91.008,63.729 91.669,64.389 103.251,64.389 114.249,53.391 114.249,50.228 113.576,49.555 106.629,49.555 105.021,47.947 PCI1.B45
G4: PCI1.B44
G5: PCI1.B46
G6: PCI1.B48 u1.4 | length 78.6
  Top Layer w0.4: u1.4 99.568,90.424 115.646,90.424 117.729,88.341 117.729,59.665 116.129,58.064 116.129,49.174 114.935,47.981 110.431,47.981 108.831,46.38 PCI1.B48
G7: PCI1.B50 u1.5 | length 86.9
  Top Layer w0.4: u1.5 94.615,95.377 99.111,95.377 100.609,93.878 121.793,93.878 122.428,93.243 122.428,60.287 116.84,54.699 116.84,47.325 113.911,44.396 PCI1.B50
G8: PCI1.B60 u1.6 | length 93.9
  Top Layer w0.4: u1.6 92.075,95.377 92.075,97.333 92.71,97.968 101.117,97.968 102.489,96.596 v1(123.495,96.596) ; PCI1.B60 126.611,46.22 v1(127.203,46.812)
  Bottom Layer w0.4: v1(123.495,96.596) 127.483,92.608 127.483,47.092 v1(127.203,46.812)
G9: PCI1.B58 u1.8 | length 87.4
  Top Layer w0.4: u1.8 97.028,87.884 v1(111.373,87.884) ; v1(121.691,52.603) 124.071,50.224 PCI1.B58
  Bottom Layer w0.4: v1(111.373,87.884) 111.373,50.044 112.192,49.225 120.117,49.225 121.691,50.8 v1(121.691,52.603)
G10: PCI1.B56
G11: PCI1.B54
G12: PCI1.B53 u1.63 | length 78.3
  Top Layer w0.4: PCI1.B53 117.721,43.274 121.793,47.346 v1(121.793,48.108)
  Bottom Layer w0.4: u1.63 103.302,91.77 103.302,99.035 103.759,99.492 105.696,99.492 117.246,87.941 117.246,65.761 122.936,60.071 122.936,49.251 v1(121.793,48.108)
G13: PCI1.B55 u1.64 | length 75.6
  Top Layer w0.4: u1.64 102.006,92.862 119.786,92.862 121.209,91.44 v1(121.209,78.257) ; PCI1.B55 120.261,44.442 121.285,45.466 v1(122.657,45.466)
  Bottom Layer w0.4: v1(121.209,78.257) 123.647,75.819 123.647,46.457 v1(122.657,45.466)
G14: PCI1.B57 u1.62 | length 66.5
  Top Layer w0.4: v1(121.717,44.044) 122.352,44.044 122.801,43.594 PCI1.B57
  Bottom Layer w0.4: u1.62 101.981,88.011 101.981,86.207 102.717,85.471 110.49,85.471 110.668,85.293 110.668,48.616 115.24,44.044 v1(121.717,44.044)
G15: PCI1.B59 u1.1 | length 82.2
  Top Layer w0.4: u1.1 98.628,96.444 99.034,96.444 100.66,94.818 122.301,94.818 127.483,89.637 127.483,49.124 125.341,46.982 PCI1.B59
LED1: PCI1.A13
LED2: PCI1.B10
LED3: C1.2 PCI1.A1 PCI1.A22 PCI1.A31 PCI1.A40 PCI1.A60 PCI1.B1 PCI1.B17 PCI1.B26 PCI1.B34 PCI1.B43 PCI1.B52 u1.9 u1.20 u1.25 u1.41 | length 438
  Top Layer w0.4: PCI1.B1 v1@49.141,47.998 ; v1(49.149,48.006) v1@49.141,47.998 ; v1(51.587,100.025) 49.141,97.579 v1(49.141,52.375) ; v1(54.864,95.86) 60.808,95.86 63.348,93.32 78.105,93.32 79.121,92.304 79.121,90.297 u1.20 82.169,89.154 86.995,93.98 86.995,95.631 u1.9 ; PCI1.B17 v1(69.461,44.399) 69.461,45.849 67.869,47.441 67.869,52.451 66.904,53.416 61.796,53.416 59.919,51.538 57.506,51.538 56.669,52.375 v1(49.141,52.375) ; PCI1.B26 80.891,43.18 81.882,44.171 83.287,44.171 84.069,44.953 84.069,60.96 84.958,61.849 86.303,61.849 86.843,61.309 89.256,61.309 90.786,62.84 v1(92.202,62.84) ; v1(90.416,45.364) 91.051,44.729 ; PCI1.B34 91.051,44.729 ; v1(93.746,62.744) 94.68,63.678 101.03,63.678 102.481,62.227 102.481,48.303 ; v1(94.259,80.137) 111.1,80.137 111.723,79.514 C1.2 ; v1(94.793,52.756) 94.793,52.095 91.051,48.354 91.051,45.364 91.051,44.729 ; PCI1.B43 102.481,48.303 ; v1(112.573,51.105) 111.735,50.267 104.445,50.267 102.481,48.303 ; PCI1.B52 116.451,43.096 118.872,45.517 v1@118.872,50.47 ; v1(119.075,50.673) v1@118.872,50.47 ; v1(126.263,49.632) 126.263,50.114 122.555,53.823 120.968,53.823 118.872,51.727 118.872,50.673 v1@118.872,50.47 ; v1@49.141,47.998 49.141,48.006 v1(49.141,52.375)
  Bottom Layer w0.4: PCI1.A1 v1@49.141,47.998 ; v1(49.141,52.375) 49.141,48.006 v1@49.141,47.998 ; v1(49.149,48.006) v1@49.141,47.998 ; v1(51.587,100.025) 54.864,96.749 v1(54.864,95.86) ; v1(69.461,44.399) 75.362,44.399 75.811,43.95 PCI1.A22 ; u1.25 76.708,82.804 76.708,87.884 u1.20 ; PCI1.A31 87.241,43.706 88.9,45.364 v1(90.416,45.364) ; u1.9 89.433,95.479 89.433,91.973 90.297,91.11 90.297,84.099 v1(94.259,80.137) ; u1.41 90.678,67.386 92.202,65.862 ; v1(92.202,62.84) 92.202,65.862 ; v1(93.746,62.744) 94.412,62.078 ; PCI1.A40 98.671,44.018 94.793,47.897 v1(94.793,52.756) 94.412,53.137 94.412,62.078 ; v1(112.573,51.105) 112.573,76.771 C1.2 115.316,62.052 115.291,62.027 115.291,54.458 v1(119.075,50.673) ; v1(126.263,49.632) 125.984,49.352 125.984,45.56 126.611,44.933 PCI1.A60 ; 92.202,65.862 94.412,63.652 94.412,62.744 94.412,62.078
LED9: PCI1.A49
MCLR: D1.2 PCI1.A8 | length 87.7
  Top Layer w0.4: v1(58.725,52.756) 58.141,53.34 51.181,53.34 49.911,54.61 49.911,93.955 54.534,98.577 57.277,98.577 58.522,99.822 D1.2@73.66,99.822
  Bottom Layer w0.4: PCI1.A8 58.031,43.629 58.369,43.967 58.369,52.4 v1(58.725,52.756)
NetC1_1: C1.1 u1.56 | length 15.6
  Top Layer w0.4: u1.56 101.981,82.677 113.653,82.677 C1.1
NetR1_2: R1.2 u1.7 | length 3.3
  Bottom Layer w0.4: u1.7 R1.2
PGC: JP1.2 PCI1.A6 | length 66.1
  Top Layer w0.4: v1(56.261,55.321) 52.121,59.461 52.121,90.83 54.94,93.65 61.798,93.65 JP1.2
  Bottom Layer w0.4: PCI1.A6 55.491,46.144 56.794,47.447 56.794,54.788 v1(56.261,55.321)
PGD: JP1.5 PCI1.A7 | length 56.8
  Top Layer w0.4: v1(55.88,87.706) 55.601,87.427 55.601,68.58 v1(56.21,67.97)
  Bottom Layer w0.4: v1(55.88,87.706) 61.798,87.706 JP1.5 ; v1(56.21,67.97) 57.506,66.675 57.506,44.526 56.761,43.782 PCI1.A7
RX: JP2.5 PCI1.A11 | length 41
  Bottom Layer w0.4: PCI1.A11 61.841,44.502 59.785,46.558 59.785,49.936 60.935,51.086 60.935,67.132 58.953,69.113 58.953,73.66 60.274,74.981 62.179,74.981 JP2.5
TX: JP2.2 PCI1.A12 | length 31.4
  Bottom Layer w0.4: PCI1.A12 63.111,44.763 62.382,45.491 62.382,70.002 JP2.2
VDD3.3V: D1.1 PCI1.A3 PCI1.A59 R1.1 u1.10 u1.19 u1.26 u1.38 u1.57 | length 228.4
  Top Layer w0.4: v1(62.992,98.044) 88.824,98.044 89.281,97.587 89.281,95.377 u1.10 ; u1.19 76.2,89.154 77.343,88.011 85.014,88.011 88.138,91.135 u1.10 ; u1.26 v1(85.598,81.534) 90.881,81.534 92.786,83.439 ; 83.058,98.044 R1.1 ; v1(114.402,84.074) u1.57 102.108,85.344 94.691,85.344 92.786,83.439 ; v1(121.691,56.794) 124.892,53.594 v1(126.136,53.594) ; u1.10 92.786,89.586 92.786,83.439
  Bottom Layer w0.4: PCI1.A3 51.681,45.745 53.289,47.353 53.289,49.073 52.095,50.267 52.095,90.119 60.02,98.044 v1(62.992,98.044) ; D1.1 R1.1 ; u1.38 85.598,77.8 85.623,77.826 85.623,81.509 v1(85.598,81.534) ; v1(114.402,84.074) 116.459,82.017 116.459,63.195 121.691,57.963 v1(121.691,56.794) ; PCI1.A59 125.341,42.596 125.146,42.596 125.146,48.736 125.063,48.819 125.063,52.521 v1(126.136,53.594)
VDD5V: PCI1.A2 PCI1.A58 | length 190.7
  Bottom Layer w0.4: PCI1.A2 50.411,48.065 50.368,48.108 50.368,100.965 51.308,102.362 ; 51.181,102.286 113.335,102.286 ; 113.284,102.362 124.358,90.754 124.358,44.813 124.071,44.526 PCI1.A58
pads on no net: nuevo.1 nuevo.2 nuevo.3 nuevo.4 nuevo.5 nuevo.6 nuevo.7 nuevo.8 nuevo.9 nuevo.10 nuevo.11 nuevo.12 nuevo.13 nuevo.14 nuevo.15 nuevo.16 nuevo.17 nuevo.18 nuevo.19 nuevo.20 nuevo.21 nuevo.22 nuevo.23 nuevo.24 nuevo.25 nuevo.26 nuevo.27 nuevo.28 nuevo.29 nuevo.30 nuevo.31 nuevo.32 nuevo.33 nuevo.34 nuevo.35 nuevo.36 nuevo.37 nuevo.38 nuevo.39 nuevo.40 nuevo.41 nuevo.42 nuevo.43 nuevo.44 nuevo.45 nuevo.46 nuevo.47 nuevo.48 nuevo.49 nuevo.50 nuevo.51 nuevo.52 nuevo.53 nuevo.54 nuevo.55 nuevo.56 nuevo.57 nuevo.58 nuevo.59 nuevo.60 nuevo.61 nuevo.62 nuevo.63 nuevo.64
copper on no net: | length 132.3
  Bottom Layer w0.254: 43.434,45.72 43.942,44.196 ; 43.434,110.998 43.942,112.522 ; 43.688,44.196 44.196,44.196 ; 43.688,112.522 44.196,112.522 ; 43.942,70.335 43.942,44.196 ; 43.942,86.383 43.942,112.522 ; 44.45,45.72 43.942,44.196 ; 44.45,110.998 43.942,112.522 ; 46.99,115.062 46.99,115.57 ; 48.513,114.806 46.99,115.316 ; 48.515,115.822 46.99,115.316 ; 79.543,115.266 46.99,115.316 ; 96.352,115.239 128.905,115.189 ; 127.38,114.683 128.905,115.189 ; 127.382,115.699 128.905,115.189 ; 128.905,114.935 128.905,115.443

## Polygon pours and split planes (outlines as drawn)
LED3 on Top Layer (hatched 90Degree grid 1 track 1.5): 48.012,111.506 128.276,111.506 128.276,44.45 48.012,44.45
LED3 on Bottom Layer (hatched 90Degree grid 1 track 1): 47.72,111.76 127.984,111.76 127.984,45.212 47.72,45.212

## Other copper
Top Layer:
  text "Zocalo dsPIC33FJxxxx6 compatible dsRRBOARD" at 55.88,107.188 h1.6
  text "Nocturno - 2006" at 54.102,104.648 h1.6
  text "www.elrebujito.es" at 95.631,104.394 h1.6
  text "Programacion" at 58.039,85.344 h1
  text "C14 / PGC / B6" at 56.769,83.439 h1
  text "C13 / PGD / B7" at 56.769,81.788 h1
  text "USART1 / USART2" at 56.388,65.659 h1
  text "F2 / RX / F4" at 58.039,63.754 h1
  text "F3 / TX / F5" at 58.039,61.849 h1
Bottom Layer:
  text "81.9151 (mm)" at 79.795,114.351 h1.52 r359.91
  text "Zocalo dsPIC33FJxxxx6 compatible dsRRBOARD" at 120.904,107.188 h1.6
  text "www.elrebujito.es" at 79.248,104.521 h1.6
  text "Nocturno - 2006" at 120.904,104.14 h1.6
  text "68.326 (mm)" at 44.856,70.589 h1.52 r90

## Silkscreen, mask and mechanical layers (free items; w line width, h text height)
Mechanical 1:
  lines w0.3: 47.516,44.304 47.516,110.516 48.725,111.725 127.5,111.725 128.325,110.9 128.325,44.35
